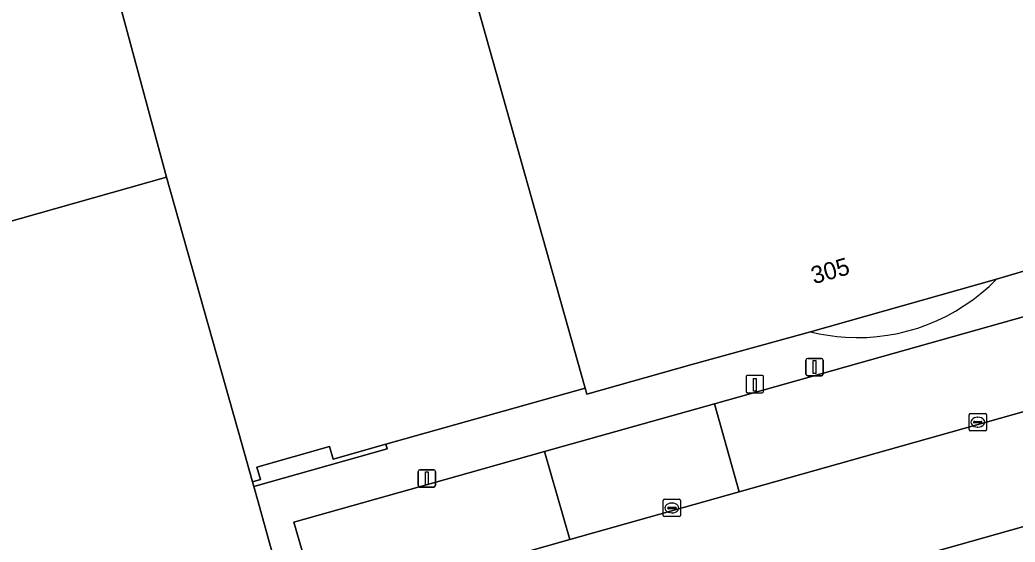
# Model space of a CAD drawing. Extents: x 159680 to 160786, y 387323 to 388340.
# Drawn here: x 159858.1 to 159915.5, y 388138.6 to 388168.7 of the extents above; entities that cross this region are included whole.
import ezdxf

# ---------------------------------------------------------------- set-up
doc = ezdxf.new("R2010")
doc.units = 0
for name, color, linetype in [('IMGEO_Erf', 7, 'Continuous'), ('IMGEO_Kolk', 7, 'Continuous'), ('IMGEO_Laadpaal', 7, 'Continuous'), ('IMGEO_Lichtmast', 7, 'Continuous'), ('IMGEO_Pand', 7, 'Continuous'), ('IMGEO_Pand_nummerreeks', 7, 'Continuous'), ('IMGEO_Pand_overbouw', 7, 'Continuous'), ('IMGEO_Parkeervlak_open', 7, 'Continuous'), ('IMGEO_Rijbaan_lokaal_gesloten', 7, 'Continuous'), ('IMGEO_Voetpad_open', 7, 'Continuous')]:
    doc.layers.add(name, color=color, linetype=linetype)

msp = doc.modelspace()

# ---------------------------------------------------------------- linework, layer by layer
at = {"layer": 'IMGEO_Erf'}
msp.add_lwpolyline([(159871.518, 388142.045), (159870.899, 388144.234), (159866.555, 388159.609), (159837.92, 388151.518), (159837.472, 388153.106), (159831.764, 388151.493), (159839.88, 388122.764), (159845.753, 388124.456), (159856.524, 388127.56), (159862.486, 388129.241), (159874.181, 388132.474), (159871.844, 388140.895), (159871.595, 388141.772)], close=True, dxfattribs=at)
at = {"layer": 'IMGEO_Kolk'}
for p, q in [((159912.875, 388145.057), (159912.875, 388145.909)), ((159912.95, 388145.983), (159913.802, 388145.983)), ((159913.363, 388145.763), (159913.388, 388145.763)), ((159913.876, 388145.909), (159913.876, 388145.057)), ((159913.802, 388144.983), (159912.95, 388144.983)), ((159913.134, 388145.477), (159913.134, 388145.489)), ((159913.572, 388145.44), (159913.174, 388145.44)), ((159913.177, 388145.526), (159913.575, 388145.526)), ((159913.386, 388145.203), (159913.361, 388145.203)), ((159913.618, 388145.489), (159913.618, 388145.477)), ((159895.223, 388140.107), (159895.223, 388140.959)), ((159895.298, 388141.033), (159896.15, 388141.033)), ((159896.224, 388140.959), (159896.224, 388140.107)), ((159895.482, 388140.527), (159895.482, 388140.539)), ((159895.92, 388140.49), (159895.522, 388140.49)), ((159895.525, 388140.576), (159895.923, 388140.576)), ((159895.711, 388140.813), (159895.736, 388140.813)), ((159895.966, 388140.539), (159895.966, 388140.527)), ((159896.15, 388140.033), (159895.298, 388140.033)), ((159895.734, 388140.253), (159895.709, 388140.253))]:
    msp.add_line(p, q, dxfattribs=at)
for points in [[(159912.875, 388145.057), (159912.875, 388145.909)], [(159912.95, 388145.983), (159913.802, 388145.983)], [(159913.876, 388145.909), (159913.876, 388145.057)], [(159913.802, 388144.983), (159912.95, 388144.983)], [(159895.223, 388140.107), (159895.223, 388140.959)], [(159895.298, 388141.033), (159896.15, 388141.033)], [(159896.224, 388140.959), (159896.224, 388140.107)], [(159896.15, 388140.033), (159895.298, 388140.033)]]:
    msp.add_lwpolyline(points, dxfattribs=at)
for centre, radius, start, end in [((159912.952, 388145.907), 0.0765, 91.55205, 178.44795), ((159912.952, 388145.907), 0.0765, 91.55205, 178.44795), ((159913.8, 388145.907), 0.0765, 1.55205, 88.44795), ((159913.8, 388145.907), 0.0765, 1.55205, 88.44795), ((159912.952, 388145.059), 0.0765, 181.55205, 268.44795), ((159912.952, 388145.059), 0.0765, 181.55205, 268.44795), ((159913.174, 388145.486), 0.0403, 85.87752, 175.75265), ((159913.171, 388145.476), 0.0366, 178.93798, 274.71019), ((159913.575, 388145.483), 0.043, 264.86636, 352.45326), ((159913.579, 388145.488), 0.0386, 1.73085, 96.63898), ((159913.8, 388145.059), 0.0765, 271.55205, 358.44795), ((159913.8, 388145.059), 0.0765, 271.55205, 358.44795), ((159895.3, 388140.957), 0.0765, 91.55205, 178.44795), ((159895.3, 388140.957), 0.0765, 91.55205, 178.44795), ((159896.148, 388140.957), 0.0765, 1.55205, 88.44795), ((159896.148, 388140.957), 0.0765, 1.55205, 88.44795), ((159895.522, 388140.536), 0.0403, 85.87752, 175.75265), ((159895.519, 388140.526), 0.0366, 178.93798, 274.71019), ((159895.923, 388140.533), 0.043, 264.86636, 352.45326), ((159895.927, 388140.538), 0.0386, 1.73085, 96.63898), ((159895.3, 388140.109), 0.0765, 181.55205, 268.44795), ((159895.3, 388140.109), 0.0765, 181.55205, 268.44795), ((159896.148, 388140.109), 0.0765, 271.55205, 358.44795), ((159896.148, 388140.109), 0.0765, 271.55205, 358.44795)]:
    msp.add_arc(centre, radius, start, end, dxfattribs=at)
for centre, major_axis, ratio, start_param, end_param in [((159913.362, 388145.483), (-0.387, 0.002), 0.722429, 4.712389, 7.853982), ((159913.387, 388145.483), (-0.39, 0.002), 0.717154, 1.570796, 4.712389), ((159895.71, 388140.533), (-0.387, 0.002), 0.722429, 4.712389, 7.853982), ((159895.735, 388140.533), (-0.39, 0.002), 0.717154, 1.570796, 4.712389)]:
    msp.add_ellipse(centre, major_axis=major_axis, ratio=ratio, start_param=start_param, end_param=end_param, dxfattribs=at)
at = {"layer": 'IMGEO_Laadpaal'}
for p, q in [((159900.008, 388148.099), (159900.008, 388147.258)), ((159900.008, 388148.099), (159900.008, 388147.258)), ((159900.924, 388148.183), (159900.083, 388148.183)), ((159900.924, 388148.183), (159900.083, 388148.183)), ((159901.008, 388147.267), (159901.008, 388148.108)), ((159901.008, 388147.267), (159901.008, 388148.108)), ((159900.092, 388147.183), (159900.933, 388147.183)), ((159900.092, 388147.183), (159900.933, 388147.183))]:
    msp.add_line(p, q, dxfattribs=at)
msp.add_lwpolyline([(159900.423, 388147.996), (159900.583, 388147.996), (159900.583, 388147.263), (159900.423, 388147.263), (159900.423, 388147.996)], dxfattribs=at)
for centre, start, end in [((159900.086, 388148.105), 92.4484, 184.28452), ((159900.086, 388148.105), 92.4484, 184.28452), ((159900.93, 388148.105), 2.4484, 94.28452), ((159900.93, 388148.105), 2.4484, 94.28452), ((159900.086, 388147.261), 182.4484, 274.28452), ((159900.086, 388147.261), 182.4484, 274.28452), ((159900.93, 388147.261), 272.4484, 4.28452), ((159900.93, 388147.261), 272.4484, 4.28452)]:
    msp.add_arc(centre, 0.0779, start, end, dxfattribs=at)
at = {"layer": 'IMGEO_Lichtmast'}
for p, q in [((159903.461, 388148.258), (159903.461, 388149.058)), ((159903.461, 388149.058), (159903.461, 388148.258)), ((159903.561, 388149.158), (159904.351, 388149.158)), ((159904.351, 388149.158), (159903.561, 388149.158)), ((159904.451, 388149.058), (159904.451, 388148.258)), ((159904.451, 388148.258), (159904.451, 388149.058)), ((159904.351, 388148.158), (159903.561, 388148.158)), ((159903.561, 388148.158), (159904.351, 388148.158)), ((159881.184, 388142.734), (159881.974, 388142.734)), ((159881.974, 388142.734), (159881.184, 388142.734)), ((159881.084, 388141.834), (159881.084, 388142.634)), ((159881.084, 388142.634), (159881.084, 388141.834)), ((159882.074, 388142.634), (159882.074, 388141.834)), ((159882.074, 388141.834), (159882.074, 388142.634)), ((159881.974, 388141.734), (159881.184, 388141.734)), ((159881.184, 388141.734), (159881.974, 388141.734))]:
    msp.add_line(p, q, dxfattribs=at)
for points in [[(159903.881, 388149.033), (159904.031, 388149.033), (159904.031, 388148.283), (159903.881, 388148.283), (159903.881, 388149.033)], [(159881.504, 388142.609), (159881.654, 388142.609), (159881.654, 388141.859), (159881.504, 388141.859), (159881.504, 388142.609)]]:
    msp.add_lwpolyline(points, dxfattribs=at)
for centre, start, end in [((159903.561, 388149.058), 90, 180), ((159903.561, 388149.058), 90, 180), ((159904.351, 388149.058), 0, 90), ((159904.351, 388149.058), 360, 90), ((159903.561, 388148.258), 180, 270), ((159903.561, 388148.258), 180, 270), ((159904.351, 388148.258), 270, 0), ((159904.351, 388148.258), 270, 0), ((159881.184, 388142.634), 90, 180), ((159881.184, 388142.634), 90, 180), ((159881.974, 388142.634), 0, 90), ((159881.974, 388142.634), 360, 90), ((159881.184, 388141.834), 180, 270), ((159881.184, 388141.834), 180, 270), ((159881.974, 388141.834), 270, 0), ((159881.974, 388141.834), 270, 0)]:
    msp.add_arc(centre, 0.1, start, end, dxfattribs=at)
at = {"layer": 'IMGEO_Pand'}
for points in [[(159881.167, 388181.347), (159880.171, 388185.081), (159878.922, 388189.762), (159875.67, 388201.469), (159875.341, 388202.65), (159875.201, 388203.152), (159860.57, 388199.031), (159856.234, 388197.81), (159861.083, 388179.862), (159866.555, 388159.609), (159870.899, 388144.234), (159871.518, 388142.045), (159871.978, 388142.174), (159871.775, 388142.896), (159875.962, 388144.075), (159876.165, 388143.353), (159879.207, 388144.209), (159890.71, 388147.447), (159883.931, 388171.528)], [(159861.083, 388179.862), (159856.234, 388197.81), (159856.152, 388198.1), (159851.905, 388196.9), (159852.016, 388196.512), (159831.021, 388190.568), (159830.907, 388190.968), (159827.079, 388189.886), (159836.153, 388157.77), (159837.472, 388153.106), (159837.92, 388151.518), (159866.555, 388159.609)], [(159915.697, 388175.388), (159914.378, 388180.082), (159898.546, 388175.634), (159883.931, 388171.528), (159890.71, 388147.447), (159890.81, 388147.091), (159896.871, 388148.812), (159903.723, 388150.692), (159914.465, 388153.736), (159921.221, 388155.725)]]:
    msp.add_lwpolyline(points, close=True, dxfattribs=at)
at = {"layer": 'IMGEO_Pand_overbouw'}
msp.add_lwpolyline([(159914.465, 388153.736), (159903.723, 388150.692)], dxfattribs=at)
for centre, radius, start, end in [((159906.43, 388161.615), 11.254, 266.52693, 315.56306), ((159906.441, 388161.677), 11.316, 256.10296, 266.48977)]:
    msp.add_arc(centre, radius, start, end, dxfattribs=at)
at = {"layer": 'IMGEO_Parkeervlak_open'}
for points in [[(159931.275, 388150.383), (159929.871, 388155.46), (159898.176, 388146.543), (159899.607, 388141.46)], [(159888.37, 388143.784), (159883.937, 388142.537), (159873.898, 388139.724), (159875.381, 388134.615), (159879.868, 388135.898), (159889.835, 388138.706)]]:
    msp.add_lwpolyline(points, close=True, dxfattribs=at)
msp.add_lwpolyline([(159954.712, 388150.359), (159888.947, 388131.828)], dxfattribs=at)
at = {"layer": 'IMGEO_Rijbaan_lokaal_gesloten'}
for points in [[(159965.053, 388157.412), (159964.443, 388159.728), (159955.7, 388157.265), (159950.73, 388155.864), (159948.403, 388155.209), (159941.032, 388153.132), (159936.232, 388151.779), (159931.275, 388150.383), (159899.607, 388141.46), (159889.835, 388138.706), (159879.868, 388135.898), (159875.381, 388134.615), (159875.587, 388133.905), (159876.027, 388132.386)], [(159888.947, 388131.828), (159954.712, 388150.359)]]:
    msp.add_lwpolyline(points, dxfattribs=at)
at = {"layer": 'IMGEO_Voetpad_open'}
for points in [[(159968.104, 388152.848), (159967.065, 388156.651), (159966.644, 388158.572), (159964.008, 388167.646), (159952.474, 388164.43), (159949.166, 388163.518), (159945.025, 388162.376), (159940.555, 388161.144), (159934.656, 388159.49), (159928.625, 388157.8), (159921.221, 388155.725), (159914.465, 388153.736), (159903.723, 388150.692), (159896.871, 388148.812), (159890.81, 388147.091), (159890.71, 388147.447), (159879.207, 388144.209), (159879.283, 388143.937), (159871.595, 388141.772), (159871.844, 388140.895), (159874.181, 388132.474), (159862.486, 388129.241), (159856.524, 388127.56)], [(159876.027, 388132.386), (159875.587, 388133.905), (159875.381, 388134.615), (159873.898, 388139.724), (159883.937, 388142.537), (159888.37, 388143.784), (159898.176, 388146.543), (159929.871, 388155.46)]]:
    msp.add_lwpolyline(points, dxfattribs=at)
for points in [[(159898.176, 388146.543), (159888.37, 388143.784), (159889.835, 388138.706), (159899.607, 388141.46)], [(159871.595, 388141.772), (159879.283, 388143.937), (159879.207, 388144.209), (159876.165, 388143.353), (159875.962, 388144.075), (159871.775, 388142.896), (159871.978, 388142.174), (159871.518, 388142.045)]]:
    msp.add_lwpolyline(points, close=True, dxfattribs=at)

# ---------------------------------------------------------------- texts
at = {"layer": 'IMGEO_Pand_nummerreeks'}
msp.add_text('305', height=1, rotation=15.84801, dxfattribs=at).set_placement((159903.918, 388153.432))

doc.saveas('drawing.dxf')
